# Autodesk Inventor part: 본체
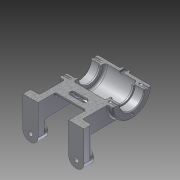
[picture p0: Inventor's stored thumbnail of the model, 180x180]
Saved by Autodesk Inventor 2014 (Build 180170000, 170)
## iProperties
Created: 2015-11
Part Number: 본체
Material: 알루미늄 6061
Document SubType Name: Modeling
Designer: Owner
Density: 2.71 g/cm^3
Appearance: 알루미늄 - 평지
Mass: 357.823 g
Surface Area: 457.813 cm^2
Volume: 132.038 cm^3
Author: Owner
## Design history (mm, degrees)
sketch "스케치1"
  geometry: L1 (-35, 25)-(35, 25); L2 (35, 25)-(35, 16); L3 (-35, 16)-(-35, 25); L4 (35, 16)-(23, 16); L5 (23, 16)-(23, 14); L6 (23, 14)-(21, 14); L7 (21, 14)-(21, 21); L8 (21, 21)-(-21, 21); L9 (-21, 21)-(-21, 14); L10 (-21, 14)-(-23, 14); L11 (-23, 14)-(-23, 16); L12 (-23, 16)-(-35, 16); L13 (-49, 0)-(49, 0) reference; L14 (0, 30)-(0, -5) reference; 1 further point
  constraints: 24 end point, 6 parallel, 3 collinear, 3 perpendicular, 1 horizontal, 2 other
  dimensions: "d0" = 28 diameter of L6 L13; "d2" = 42 diameter of L8 L13; "d3" = 70 distance between parallel lines of L3 L2; "d4" = 32 diameter of L4 L13; "d5" = 42 distance between parallel lines of L7 L9; "d6" = 50 diameter of L1 L13; "d7" = 12 distance between parallel lines of L2 L5; "d8" = 12 distance between parallel lines of L3 L11 (= d7)
revolve "회전1" sketch "스케치1" stored, may be unused: angle "d9" = 90 deg
node "작업 평면1"
sketch "스케치2"
  geometry: L1 (0, -35)-(0, 35) reference; L2 (-49, 0)-(49, 0) reference; L3 (40, -40)-(40, 40); L4 (20, 40)-(20, 35); L5 (20, 35)-(20, -40); L6 (-20, -40)-(-20, 40); L7 (-40, 40)-(-40, -40); A1 r 10 centre (-30, -40) between (-40, -40) and (-20, -40); A2 r 10 centre (-30, 40) between (-20, 40) and (-40, 40); A3 r 10 centre (30, -40) between (20, -40) and (40, -40); A4 r 10 centre (30, 40) between (40, 40) and (20, 40); 1 further point
  constraints: 10 end point, 8 point on circle, 7 tangent, 4 centre point, 2 horizontal alignment, 2 symmetric about line, 2 vertical alignment, 1 parallel
  dimensions: "d11" = 10 radius of A1; "d12" = 10 radius of A2; "d13" = 10 radius of A3; "d14" = 10 radius of A4; "d15" = 80 distance of A2.centre A1.centre; "d16" = 40 distance between parallel lines of L1 L3
extrude "돌출1" join sketch "스케치2" distance "d17" = 10; taper "d18" = 0 deg
sketch "스케치3"
  geometry: L1 (40, 40)-(40, -40) reference; L2 (20, -40)-(20, 40) reference; A1 r 10 centre (-30, 40) between (-20, 40) and (-40, 40) reference; A2 r 10 centre (-30, -40) between (-40, -40) and (-20, -40) reference; A3 r 10 centre (30, 40) between (40, 40) and (20, 40) reference; A4 r 10 centre (30, -40) between (20, -40) and (40, -40) reference; 5 further points
  constraints: 4 coincident, 4 horizontal alignment, 8 other
extrude "돌출2" join sketch "스케치3" distance "d19" = 3; taper "d20" = 0 deg
sketch "스케치4"
  geometry: L1 (40, 40)-(40, -40) reference; L2 (20, -40)-(20, 40) reference; L3 (-20, 40)-(-20, -40) reference; L4 (-40, -40)-(-40, 40) reference; L5 (-20, -4)-(20, -4); L6 (20, 4)-(-20, 4); L7 (20, -25)-(28, -25); L8 (28, -25)-(28, 25); L9 (28, 25)-(20, 25); L10 (-20, -25)-(-28, -25); L11 (-28, -25)-(-28, 25); L12 (-28, 25)-(-20, 25); L13 (0, 70)-(0, -70) reference; L14 (56, 0)-(-56, 0) reference; L15 (-20, 25)-(-20, 4); L16 (-20, -4)-(-20, -25); L17 (20, 25)-(20, 4); L18 (20, -4)-(20, -25); A1 r 10 centre (30, 40) between (40, 40) and (20, 40) reference; A2 r 10 centre (30, -40) between (20, -40) and (40, -40) reference; A3 r 10 centre (-30, 40) between (-20, 40) and (-40, 40) reference; A4 r 10 centre (-30, -40) between (-40, -40) and (-20, -40) reference; 1 further point
  constraints: 24 end point, 7 parallel, 4 collinear, 3 horizontal, 2 perpendicular, 2 point on line, 2 other
  dimensions: "d21" = 8 distance between parallel lines of L5 L6; "d22" = 8 distance between parallel lines of L3 L11; "d23" = 8 distance between parallel lines of L8 L17; "d24" = 50 distance between parallel lines of L10 L12
extrude "돌출3" join sketch "스케치4" stored distance "d25" = 3; taper "d26" = 0 deg
sketch "스케치5"
  geometry: L1 (0, 33.322)-(40, 33.322) reference; L2 (40, 0)-(40, 33.322) reference; L3 (12, 23)-(28, 23); L4 (12, 19.5)-(28, 19.5); L5 (28, 26.5)-(12, 26.5); L6 (0, 0)-(40, 0); L7 (40, 0)-(40, 13); L8 (40, 13)-(0, 13); L9 (0, 13)-(0, 0); L10 (40, -10)-(60, -10) reference; L11 (20, -28.6)-(20, 101.6) reference; L12 (55, 33)-(-15, 33) reference; A1 r 3.5 centre (12, 23) between (12, 26.5) and (12, 19.5); A2 r 3.5 centre (28, 23) between (28, 19.5) and (28, 26.5); 2 further points
  constraints: 16 end point, 4 parallel, 4 point on circle, 4 tangent, 2 centre point, 1 horizontal, 1 midpoint, 1 perpendicular, 1 point on line, 1 symmetric about line
  dimensions: "d29" = 3.5 radius of A2; "d30" = 33 distance between parallel lines of L10 L3; "d32" = 16 distance of L3.start L3.end; "d90" = 20 distance between parallel lines of L8 L12
extrude "돌출4" cut sketch "스케치5" stored distance "d33" = 3; taper "d34" = 0 deg
fillet "모깎기1" dims "d35" = 3
fillet "모깎기2" dims "d36" = 0.3
sketch "스케치6" dims "d37" = 40
  geometry: L1 (-70, 0)-(70, 0) reference; L2 (0, 43.6)-(0, -86.6) reference; C1 r 16 at (0, 0) reference; 2 further points
  constraints: 1 coincident, 1 point on line, 1 vertical alignment, 2 other
hole "구멍1" sketch "스케치6" at (0, 20) diameter "d38" = 3.242; stored, may be unused: countersink angle "d42" = 90 deg, drill point angle "d44" = 118 deg; dims "d39" = 8, "d40" = 4, "d41" = 2, "d43" = 10
sketch "스케치7"
  geometry: L1 (30, 30)-(30, -110) reference; L2 (86, -40)-(-26, -40) reference; 4 further points
  constraints: 2 symmetric about line, 2 vertical alignment, 1 horizontal alignment
  dimensions: "d48" = 80 distance of point (60, -80) point (60, 0); "d49" = 60 distance of point (0, 0) point (60, 0)
hole "구멍2" sketch "스케치7" at (0, 0), (60, 0), (60, -80), (0, -80) diameter "d50" = 6; stored, may be unused: countersink angle "d54" = 90 deg, drill point angle "d56" = 118 deg; dims "d51" = 8, "d52" = 12, "d53" = 4, "d55" = 4
fillet "모깎기3" dims "d57" = 0.3
chamfer "모따기1" distance "d58" = 1; stored, may be unused: second distance "d59" = 2, angle "d60" = 45 deg
fillet "모깎기4" dims "d61" = 2
chamfer "모따기2" distance "d62" = 1; stored, may be unused: second distance "d63" = 2, angle "d64" = 45 deg
node "작업 평면3"
  node "작업 평면2"
sketch "스케치8"
  geometry: L1 (-20.739, -11.15)-(20.739, -11.15); L2 (20.739, -11.15)-(20.739, 11.15); L3 (20.739, 11.15)-(-20.739, 11.15); L4 (-20.739, 11.15)-(-20.739, -11.15); 3 further points
  constraints: 2 midpoint, 1 horizontal alignment, 1 vertical alignment, 2 other
feature "엠보싱1" sketch "스케치8" dims "d11" = 10, "d12" = 10, "d13" = 10, "d14" = 10, "d15" = 80, "d16" = 40, "d68" = 0.5, "d69" = 0
node "작업 평면4"
sketch "스케치10"
  geometry: C1 r 5 at (0, 0); 1 further point
  constraints: 1 centre point, 1 coincident
  dimensions: "d73" = 5 radius of C1
extrude "돌출5" join sketch "스케치10" stored distance "d74" = 3; taper "d75" = 0 deg
sketch "스케치11"
  geometry: L1 (0, 70)-(0, -70) reference; L2 (56.002, 0)-(-56.002, 0) reference; 1 further point
  constraints: 2 midpoint
hole "구멍3" sketch "스케치11" at (0, 0) diameter "d76" = 5.188; stored, may be unused: countersink angle "d80" = 90 deg, drill point angle "d82" = 118 deg; dims "d77" = 8, "d78" = 12, "d79" = 4, "d81" = 4
fillet "모깎기5" dims "d83" = 2
chamfer "모따기3" distance "d87" = 1; stored, may be unused: second distance "d88" = 2, angle "d89" = 45 deg
node "솔리드1"
pattern_circular "원형 패턴1" dims angle "d46" = 360 deg
mirror "대칭1"
pattern_circular "원형 패턴2" dims "d85" = 150 deg
node "투영된 루프1"
node "투영된 루프2"
node "투영된 루프3"
other parameters: "d10" = -68, "d65" = 0.5, "d72" = 28
